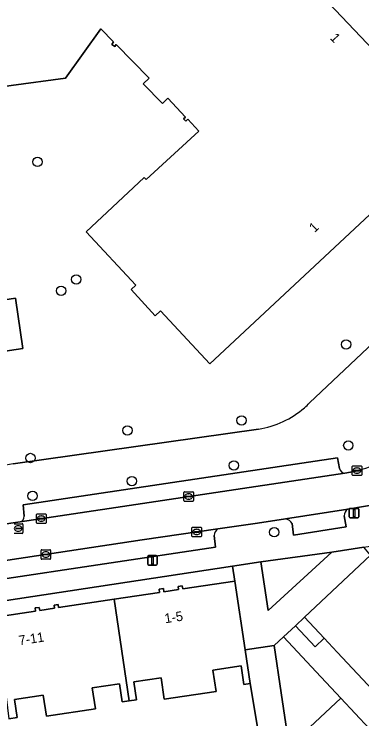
# Model space of a CAD drawing. Extents: x 162344 to 162869, y 381217 to 381818.
# Drawn here: x 162570.6 to 162607, y 381348.2 to 381421.8 of the extents above; entities that cross this region are included whole.
import ezdxf

# ---------------------------------------------------------------- set-up
doc = ezdxf.new("R2010")
doc.units = 0
for name, color, linetype in [('IMGEO_Boom', 7, 'Continuous'), ('IMGEO_Erf', 7, 'Continuous'), ('IMGEO_Kolk', 7, 'Continuous'), ('IMGEO_Lichtmast', 7, 'Continuous'), ('IMGEO_Pand', 7, 'Continuous'), ('IMGEO_Pand_nummerreeks', 7, 'Continuous'), ('IMGEO_Parkeervlak_open', 7, 'Continuous'), ('IMGEO_Rijbaan_lokaal_gesloten', 7, 'Continuous'), ('IMGEO_Rioolput', 7, 'Continuous'), ('IMGEO_Voetpad_open', 7, 'Continuous')]:
    doc.layers.add(name, color=color, linetype=linetype)

msp = doc.modelspace()

# ---------------------------------------------------------------- linework, layer by layer
at = {"layer": 'IMGEO_Boom'}
for centre in [(162573.075, 381406.392), (162577.132, 381394.132), (162575.548, 381392.937), (162605.328, 381387.344), (162594.403, 381379.412), (162582.48, 381378.367), (162605.564, 381376.788), (162572.334, 381375.481), (162593.604, 381374.7), (162582.94, 381373.073), (162572.567, 381371.525), (162597.817, 381367.723)]:
    msp.add_circle(centre, 0.489, dxfattribs=at)
at = {"layer": 'IMGEO_Erf'}
for points in [[(162603.56, 381422.951), (162608.827, 381417.399)], [(162616.655, 381409.149), (162591.074, 381385.317), (162585.928, 381390.841), (162585.389, 381390.339), (162582.851, 381393.064), (162583.337, 381393.517), (162578.148, 381399.087), (162584.24, 381404.762), (162584.436, 381404.551), (162589.953, 381409.618), (162588.787, 381410.858), (162588.584, 381410.651), (162588.35, 381410.881), (162588.56, 381411.078), (162586.71, 381413.045), (162586.136, 381412.488), (162584.135, 381414.545), (162584.732, 381415.127), (162581.294, 381418.66), (162581.163, 381418.454), (162580.845, 381418.667), (162581.033, 381418.928), (162579.712, 381420.286), (162576.009, 381415.134), (162564.593, 381413.622)], [(162601.509, 381381.232), (162620.339, 381398.978), (162622.119, 381400.656)], [(162568.257, 381391.801), (162570.791, 381392.181), (162571.557, 381386.927), (162568.969, 381386.539)], [(162570.548, 381374.856), (162596.18, 381378.489)], [(162597.05, 381341.556), (162595.307, 381351.935), (162594.646, 381351.836), (162594.35, 381353.779), (162591.412, 381353.343), (162591.75, 381351.107), (162586.331, 381350.29), (162585.993, 381352.539), (162583.137, 381352.115), (162583.426, 381350.237), (162582.674, 381350.124), (162581.923, 381350.01), (162581.635, 381351.892), (162578.794, 381351.47), (162579.122, 381349.293), (162574.004, 381348.522), (162573.673, 381350.71), (162570.656, 381350.262), (162570.941, 381348.378), (162570.076, 381348.247)]]:
    msp.add_lwpolyline(points, dxfattribs=at)
for points in [[(162593.693, 381362.637), (162593.458, 381364.187), (162555.599, 381358.447), (162555.828, 381356.926), (162560.046, 381357.562), (162564.264, 381358.199), (162572.881, 381359.499), (162572.832, 381359.826), (162573.257, 381359.89), (162573.306, 381359.563), (162574.858, 381359.797), (162574.809, 381360.124), (162575.234, 381360.188), (162575.283, 381359.861), (162581.074, 381360.735), (162585.843, 381361.454), (162585.794, 381361.781), (162586.229, 381361.846), (162586.278, 381361.519), (162587.83, 381361.753), (162587.781, 381362.08), (162588.206, 381362.144), (162588.255, 381361.817)], [(162604.402, 381355.204), (162603.04, 381356.655), (162602.103, 381355.775), (162600.043, 381357.97), (162598.783, 381356.808), (162602.205, 381353.162), (162604.783, 381350.416), (162607.786, 381347.217), (162610.83, 381343.974), (162613.666, 381340.953), (162618.167, 381336.158), (162620.355, 381338.212)]]:
    msp.add_lwpolyline(points, close=True, dxfattribs=at)
for centre, radius, start, end in [((162594.649, 381388.016), 9.649, 279.12953, 311.01266), ((162594.528, 381388.12), 9.807, 311.1491, 315.38626)]:
    msp.add_arc(centre, radius, start, end, dxfattribs=at)
at = {"layer": 'IMGEO_Kolk'}
for p, q in [((162605.967, 381373.737), (162605.967, 381374.589)), ((162606.042, 381374.663), (162606.894, 381374.663)), ((162606.226, 381374.157), (162606.226, 381374.169)), ((162606.664, 381374.12), (162606.266, 381374.12)), ((162606.269, 381374.206), (162606.667, 381374.206)), ((162606.455, 381374.443), (162606.48, 381374.443)), ((162606.71, 381374.169), (162606.71, 381374.157)), ((162606.968, 381374.589), (162606.968, 381373.737)), ((162606.894, 381373.663), (162606.042, 381373.663)), ((162606.478, 381373.883), (162606.453, 381373.883)), ((162588.373, 381371.03), (162588.373, 381371.882)), ((162588.448, 381371.956), (162589.3, 381371.956)), ((162589.374, 381371.882), (162589.374, 381371.03)), ((162588.632, 381371.45), (162588.632, 381371.462)), ((162589.07, 381371.413), (162588.672, 381371.413)), ((162588.675, 381371.499), (162589.073, 381371.499)), ((162588.884, 381371.176), (162588.859, 381371.176)), ((162588.861, 381371.736), (162588.886, 381371.736)), ((162589.116, 381371.462), (162589.116, 381371.45)), ((162589.3, 381370.956), (162588.448, 381370.956)), ((162573.045, 381369.653), (162573.897, 381369.653)), ((162572.97, 381368.727), (162572.97, 381369.579)), ((162573.229, 381369.147), (162573.229, 381369.159)), ((162573.667, 381369.11), (162573.269, 381369.11)), ((162573.272, 381369.196), (162573.67, 381369.196)), ((162573.481, 381368.873), (162573.456, 381368.873)), ((162573.458, 381369.433), (162573.483, 381369.433)), ((162573.713, 381369.159), (162573.713, 381369.147)), ((162573.971, 381369.579), (162573.971, 381368.727)), ((162573.897, 381368.653), (162573.045, 381368.653)), ((162589.215, 381367.334), (162589.215, 381368.186)), ((162589.29, 381368.26), (162590.142, 381368.26)), ((162590.216, 381368.186), (162590.216, 381367.334)), ((162589.474, 381367.754), (162589.474, 381367.766)), ((162589.912, 381367.717), (162589.514, 381367.717)), ((162589.517, 381367.803), (162589.915, 381367.803)), ((162589.726, 381367.48), (162589.701, 381367.48)), ((162589.703, 381368.04), (162589.728, 381368.04)), ((162589.958, 381367.766), (162589.958, 381367.754)), ((162590.142, 381367.26), (162589.29, 381367.26)), ((162573.449, 381364.981), (162573.449, 381365.833)), ((162573.524, 381365.907), (162574.376, 381365.907)), ((162573.708, 381365.401), (162573.708, 381365.413)), ((162574.146, 381365.364), (162573.748, 381365.364)), ((162573.751, 381365.45), (162574.149, 381365.45)), ((162573.937, 381365.687), (162573.962, 381365.687)), ((162574.192, 381365.413), (162574.192, 381365.401)), ((162574.45, 381365.833), (162574.45, 381364.981)), ((162574.376, 381364.907), (162573.524, 381364.907)), ((162573.96, 381365.127), (162573.935, 381365.127))]:
    msp.add_line(p, q, dxfattribs=at)
for points in [[(162605.967, 381373.737), (162605.967, 381374.589)], [(162606.042, 381374.663), (162606.894, 381374.663)], [(162606.968, 381374.589), (162606.968, 381373.737)], [(162606.894, 381373.663), (162606.042, 381373.663)], [(162588.373, 381371.03), (162588.373, 381371.882)], [(162588.448, 381371.956), (162589.3, 381371.956)], [(162589.374, 381371.882), (162589.374, 381371.03)], [(162589.3, 381370.956), (162588.448, 381370.956)], [(162573.045, 381369.653), (162573.897, 381369.653)], [(162572.97, 381368.727), (162572.97, 381369.579)], [(162573.971, 381369.579), (162573.971, 381368.727)], [(162573.897, 381368.653), (162573.045, 381368.653)], [(162589.215, 381367.334), (162589.215, 381368.186)], [(162589.29, 381368.26), (162590.142, 381368.26)], [(162590.216, 381368.186), (162590.216, 381367.334)], [(162590.142, 381367.26), (162589.29, 381367.26)], [(162573.449, 381364.981), (162573.449, 381365.833)], [(162573.524, 381365.907), (162574.376, 381365.907)], [(162574.45, 381365.833), (162574.45, 381364.981)], [(162574.376, 381364.907), (162573.524, 381364.907)]]:
    msp.add_lwpolyline(points, dxfattribs=at)
for centre, radius, start, end in [((162606.044, 381374.587), 0.0765, 91.55205, 178.44795), ((162606.044, 381374.587), 0.0765, 91.55205, 178.44795), ((162606.266, 381374.166), 0.0403, 85.87752, 175.75265), ((162606.263, 381374.156), 0.0366, 178.93798, 274.71019), ((162606.667, 381374.163), 0.043, 264.86636, 352.45326), ((162606.671, 381374.168), 0.0386, 1.73085, 96.63898), ((162606.892, 381374.587), 0.0765, 1.55205, 88.44795), ((162606.892, 381374.587), 0.0765, 1.55205, 88.44795), ((162606.044, 381373.739), 0.0765, 181.55205, 268.44795), ((162606.044, 381373.739), 0.0765, 181.55205, 268.44795), ((162606.892, 381373.739), 0.0765, 271.55205, 358.44795), ((162606.892, 381373.739), 0.0765, 271.55205, 358.44795), ((162588.45, 381371.88), 0.0765, 91.55205, 178.44795), ((162588.45, 381371.88), 0.0765, 91.55205, 178.44795), ((162589.298, 381371.88), 0.0765, 1.55205, 88.44795), ((162589.298, 381371.88), 0.0765, 1.55205, 88.44795), ((162588.672, 381371.459), 0.0403, 85.87752, 175.75265), ((162588.669, 381371.449), 0.0366, 178.93798, 274.71019), ((162589.073, 381371.456), 0.043, 264.86636, 352.45326), ((162589.077, 381371.461), 0.0386, 1.73085, 96.63898), ((162588.45, 381371.032), 0.0765, 181.55205, 268.44795), ((162588.45, 381371.032), 0.0765, 181.55205, 268.44795), ((162589.298, 381371.032), 0.0765, 271.55205, 358.44795), ((162589.298, 381371.032), 0.0765, 271.55205, 358.44795), ((162573.047, 381369.577), 0.0765, 91.55205, 178.44795), ((162573.047, 381369.577), 0.0765, 91.55205, 178.44795), ((162573.895, 381369.577), 0.0765, 1.55205, 88.44795), ((162573.895, 381369.577), 0.0765, 1.55205, 88.44795), ((162573.269, 381369.156), 0.0403, 85.87752, 175.75265), ((162573.266, 381369.146), 0.0366, 178.93798, 274.71019), ((162573.67, 381369.153), 0.043, 264.86636, 352.45326), ((162573.674, 381369.158), 0.0386, 1.73085, 96.63898), ((162573.047, 381368.729), 0.0765, 181.55205, 268.44795), ((162573.047, 381368.729), 0.0765, 181.55205, 268.44795), ((162573.895, 381368.729), 0.0765, 271.55205, 358.44795), ((162573.895, 381368.729), 0.0765, 271.55205, 358.44795), ((162589.292, 381368.184), 0.0765, 91.55205, 178.44795), ((162589.292, 381368.184), 0.0765, 91.55205, 178.44795), ((162590.14, 381368.184), 0.0765, 1.55205, 88.44795), ((162590.14, 381368.184), 0.0765, 1.55205, 88.44795), ((162589.514, 381367.763), 0.0403, 85.87752, 175.75265), ((162589.511, 381367.753), 0.0366, 178.93798, 274.71019), ((162589.915, 381367.76), 0.043, 264.86636, 352.45326), ((162589.919, 381367.765), 0.0386, 1.73085, 96.63898), ((162589.292, 381367.336), 0.0765, 181.55205, 268.44795), ((162589.292, 381367.336), 0.0765, 181.55205, 268.44795), ((162590.14, 381367.336), 0.0765, 271.55205, 358.44795), ((162590.14, 381367.336), 0.0765, 271.55205, 358.44795), ((162573.526, 381365.831), 0.0765, 91.55205, 178.44795), ((162573.526, 381365.831), 0.0765, 91.55205, 178.44795), ((162573.748, 381365.41), 0.0403, 85.87752, 175.75265), ((162573.745, 381365.4), 0.0366, 178.93798, 274.71019), ((162574.149, 381365.407), 0.043, 264.86636, 352.45326), ((162574.153, 381365.412), 0.0386, 1.73085, 96.63898), ((162574.374, 381365.831), 0.0765, 1.55205, 88.44795), ((162574.374, 381365.831), 0.0765, 1.55205, 88.44795), ((162573.526, 381364.983), 0.0765, 181.55205, 268.44795), ((162573.526, 381364.983), 0.0765, 181.55205, 268.44795), ((162574.374, 381364.983), 0.0765, 271.55205, 358.44795), ((162574.374, 381364.983), 0.0765, 271.55205, 358.44795)]:
    msp.add_arc(centre, radius, start, end, dxfattribs=at)
for centre, major_axis, ratio, start_param, end_param in [((162606.454, 381374.163), (-0.387, 0.002), 0.722429, 4.712389, 7.853982), ((162606.479, 381374.163), (-0.39, 0.002), 0.717154, 1.570796, 4.712389), ((162588.86, 381371.456), (-0.387, 0.002), 0.722429, 4.712389, 7.853982), ((162588.885, 381371.456), (-0.39, 0.002), 0.717154, 1.570796, 4.712389), ((162573.457, 381369.153), (-0.387, 0.002), 0.722429, 4.712389, 7.853982), ((162573.482, 381369.153), (-0.39, 0.002), 0.717154, 1.570796, 4.712389), ((162589.702, 381367.76), (-0.387, 0.002), 0.722429, 4.712389, 7.853982), ((162589.727, 381367.76), (-0.39, 0.002), 0.717154, 1.570796, 4.712389), ((162573.936, 381365.407), (-0.387, 0.002), 0.722429, 4.712389, 7.853982), ((162573.961, 381365.407), (-0.39, 0.002), 0.717154, 1.570796, 4.712389)]:
    msp.add_ellipse(centre, major_axis=major_axis, ratio=ratio, start_param=start_param, end_param=end_param, dxfattribs=at)
at = {"layer": 'IMGEO_Lichtmast'}
for p, q in [((162605.669, 381369.326), (162605.669, 381370.126)), ((162605.669, 381370.126), (162605.669, 381369.326)), ((162605.769, 381370.226), (162606.559, 381370.226)), ((162606.559, 381370.226), (162605.769, 381370.226)), ((162606.659, 381370.126), (162606.659, 381369.326)), ((162606.659, 381369.326), (162606.659, 381370.126)), ((162606.559, 381369.226), (162605.769, 381369.226)), ((162605.769, 381369.226), (162606.559, 381369.226)), ((162584.594, 381364.386), (162584.594, 381365.186)), ((162584.594, 381365.186), (162584.594, 381364.386)), ((162584.694, 381365.286), (162585.484, 381365.286)), ((162585.484, 381365.286), (162584.694, 381365.286)), ((162585.584, 381365.186), (162585.584, 381364.386)), ((162585.584, 381364.386), (162585.584, 381365.186)), ((162585.484, 381364.286), (162584.694, 381364.286)), ((162584.694, 381364.286), (162585.484, 381364.286))]:
    msp.add_line(p, q, dxfattribs=at)
for points in [[(162606.089, 381370.101), (162606.239, 381370.101), (162606.239, 381369.351), (162606.089, 381369.351), (162606.089, 381370.101)], [(162585.014, 381365.161), (162585.164, 381365.161), (162585.164, 381364.411), (162585.014, 381364.411), (162585.014, 381365.161)]]:
    msp.add_lwpolyline(points, dxfattribs=at)
for centre, start, end in [((162605.769, 381370.126), 90, 180), ((162605.769, 381370.126), 90, 180), ((162606.559, 381370.126), 0, 90), ((162606.559, 381370.126), 360, 90), ((162605.769, 381369.326), 180, 270), ((162605.769, 381369.326), 180, 270), ((162606.559, 381369.326), 270, 0), ((162606.559, 381369.326), 270, 0), ((162584.694, 381365.186), 90, 180), ((162584.694, 381365.186), 90, 180), ((162585.484, 381365.186), 0, 90), ((162585.484, 381365.186), 360, 90), ((162584.694, 381364.386), 180, 270), ((162584.694, 381364.386), 180, 270), ((162585.484, 381364.386), 270, 0), ((162585.484, 381364.386), 270, 0)]:
    msp.add_arc(centre, 0.1, start, end, dxfattribs=at)
at = {"layer": 'IMGEO_Pand'}
for points in [[(162608.827, 381417.399), (162603.56, 381422.951)], [(162564.593, 381413.622), (162576.009, 381415.134), (162579.712, 381420.286), (162581.033, 381418.928), (162580.845, 381418.667), (162581.163, 381418.454), (162581.294, 381418.66), (162584.732, 381415.127), (162584.135, 381414.545), (162586.136, 381412.488), (162586.71, 381413.045), (162588.56, 381411.078), (162588.35, 381410.881), (162588.584, 381410.651), (162588.787, 381410.858), (162589.953, 381409.618), (162584.436, 381404.551), (162584.24, 381404.762), (162578.148, 381399.087), (162583.337, 381393.517), (162582.851, 381393.064), (162585.389, 381390.339), (162585.928, 381390.841), (162591.074, 381385.317), (162616.655, 381409.149)]]:
    msp.add_lwpolyline(points, dxfattribs=at)
for points in [[(162568.969, 381386.539), (162571.557, 381386.927), (162570.791, 381392.181), (162568.257, 381391.801), (162568.071, 381391.773), (162568.838, 381386.519)], [(162607.896, 381365.343), (162600.979, 381358.849), (162603.04, 381356.655), (162604.402, 381355.204), (162620.355, 381338.212), (162623.628, 381341.285), (162627.163, 381344.605), (162627.272, 381344.707)], [(162593.693, 381362.637), (162588.255, 381361.817), (162588.206, 381362.144), (162587.781, 381362.08), (162587.83, 381361.753), (162586.278, 381361.519), (162586.229, 381361.846), (162585.794, 381361.781), (162585.843, 381361.454), (162581.074, 381360.735), (162582.674, 381350.124), (162583.426, 381350.237), (162583.137, 381352.115), (162585.993, 381352.539), (162586.331, 381350.29), (162591.75, 381351.107), (162591.412, 381353.343), (162594.35, 381353.779), (162594.646, 381351.836), (162595.307, 381351.935), (162594.778, 381355.441)], [(162581.074, 381360.735), (162575.283, 381359.861), (162575.234, 381360.188), (162574.809, 381360.124), (162574.858, 381359.797), (162573.306, 381359.563), (162573.257, 381359.89), (162572.832, 381359.826), (162572.881, 381359.499), (162564.264, 381358.199), (162565.34, 381351.082), (162569.652, 381351.706), (162570.076, 381348.247), (162570.941, 381348.378), (162570.656, 381350.262), (162573.673, 381350.71), (162574.004, 381348.522), (162579.122, 381349.293), (162578.794, 381351.47), (162581.635, 381351.892), (162581.923, 381350.01), (162582.674, 381350.124)], [(162600.979, 381358.849), (162600.043, 381357.97), (162602.103, 381355.775), (162603.04, 381356.655)], [(162602.205, 381353.162), (162598.783, 381356.808), (162597.826, 381355.908), (162598.554, 381350.962), (162599.38, 381345.353), (162604.783, 381350.416)], [(162607.786, 381347.217), (162604.783, 381350.416), (162599.38, 381345.353), (162600.158, 381340.069)]]:
    msp.add_lwpolyline(points, close=True, dxfattribs=at)
at = {"layer": 'IMGEO_Parkeervlak_open'}
for points in [[(162604.653, 381374.394), (162604.442, 381375.51), (162571.586, 381370.597), (162571.671, 381369.405)], [(162571.256, 381368.82), (162605.213, 381373.889)], [(162605.497, 381370.151), (162598.994, 381369.138)], [(162599.705, 381368.632), (162599.828, 381367.427), (162605.344, 381368.279), (162605.12, 381369.446)], [(162591.93, 381368.082), (162584.005, 381366.935), (162567.642, 381364.451)], [(162568.27, 381363.869), (162568.456, 381362.69), (162591.675, 381366.161), (162591.526, 381367.391)]]:
    msp.add_lwpolyline(points, dxfattribs=at)
for centre, radius, start, end in [((162605.245, 381374.487), 0.599, 188.96174, 266.95088), ((162606.084, 381369.384), 0.966, 127.42795, 176.30061), ((162571.158, 381369.329), 0.518, 280.85333, 8.44276), ((162598.741, 381368.03), 1.136, 31.9769, 77.14619), ((162592.583, 381367.236), 1.069, 127.69185, 171.68192)]:
    msp.add_arc(centre, radius, start, end, dxfattribs=at)
at = {"layer": 'IMGEO_Rijbaan_lokaal_gesloten'}
for points in [[(162591.93, 381368.082), (162592.402, 381368.151), (162596.083, 381368.685), (162598.994, 381369.138), (162605.497, 381370.151), (162607.148, 381370.42), (162608.866, 381370.698), (162614.045, 381372.134), (162617.725, 381373.904), (162624.41, 381379.449), (162626.115, 381381.23), (162639.652, 381395.21)], [(162606.17, 381374.078), (162605.213, 381373.889), (162571.256, 381368.82), (162570.283, 381368.666), (162564.322, 381367.722), (162563.948, 381367.663), (162563.582, 381367.608), (162535.111, 381363.294), (162534.146, 381363.156), (162524.421, 381361.762), (162523.981, 381361.699), (162522.366, 381361.45), (162515.899, 381360.453), (162513.321, 381360.055), (162512.415, 381359.993)], [(162515.923, 381356.718), (162517.595, 381356.95), (162517.749, 381356.974), (162530.674, 381358.967), (162533.107, 381359.314), (162536.811, 381359.842), (162540.681, 381360.393), (162547.682, 381361.428), (162548.639, 381361.573), (162552.34, 381362.133), (162555.362, 381362.591), (162558.977, 381363.139), (162563.502, 381363.824), (162567.132, 381364.374), (162567.642, 381364.451), (162584.005, 381366.935), (162591.93, 381368.082)]]:
    msp.add_lwpolyline(points, dxfattribs=at)
msp.add_arc((162602.584, 381388.789), 15.141, 283.69796, 309.06214, dxfattribs=at)
at = {"layer": 'IMGEO_Rioolput'}
for p, q in [((162570.628, 381368.616), (162571.48, 381368.616)), ((162570.812, 381368.11), (162570.812, 381368.122)), ((162570.855, 381368.159), (162571.253, 381368.159)), ((162571.041, 381368.396), (162571.066, 381368.396)), ((162571.296, 381368.122), (162571.296, 381368.11)), ((162571.554, 381368.542), (162571.554, 381367.69)), ((162571.48, 381367.616), (162570.628, 381367.616)), ((162571.25, 381368.073), (162570.852, 381368.073)), ((162571.064, 381367.836), (162571.039, 381367.836))]:
    msp.add_line(p, q, dxfattribs=at)
for points in [[(162570.628, 381368.616), (162571.48, 381368.616)], [(162571.554, 381368.542), (162571.554, 381367.69)], [(162571.48, 381367.616), (162570.628, 381367.616)]]:
    msp.add_lwpolyline(points, dxfattribs=at)
for centre, radius, start, end in [((162570.852, 381368.119), 0.0403, 85.87752, 175.75265), ((162571.257, 381368.121), 0.0386, 1.73085, 96.63898), ((162571.478, 381368.54), 0.0765, 1.55205, 88.44795), ((162571.478, 381368.54), 0.0765, 1.55205, 88.44795), ((162570.849, 381368.109), 0.0366, 178.93798, 274.71019), ((162571.253, 381368.116), 0.043, 264.86636, 352.45326), ((162571.478, 381367.692), 0.0765, 271.55205, 358.44795), ((162571.478, 381367.692), 0.0765, 271.55205, 358.44795)]:
    msp.add_arc(centre, radius, start, end, dxfattribs=at)
for centre, major_axis, ratio, start_param, end_param in [((162571.04, 381368.116), (-0.387, 0.002), 0.722429, 4.712389, 7.853982), ((162571.065, 381368.116), (-0.39, 0.002), 0.717154, 1.570796, 4.712389)]:
    msp.add_ellipse(centre, major_axis=major_axis, ratio=ratio, start_param=start_param, end_param=end_param, dxfattribs=at)
at = {"layer": 'IMGEO_Voetpad_open'}
for points in [[(162633.892, 381403.758), (162633.239, 381404.624), (162630.243, 381407.839), (162622.119, 381400.656), (162620.339, 381398.978), (162601.509, 381381.232)], [(162596.18, 381378.489), (162570.548, 381374.856), (162569.375, 381374.68), (162565.802, 381374.16), (162563.919, 381373.876), (162551.336, 381371.979), (162545.689, 381371.128), (162541.544, 381370.503), (162528.79, 381368.58), (162528.573, 381367.017), (162509.669, 381369.232), (162513.321, 381360.055), (162515.899, 381360.453)], [(162571.671, 381369.405), (162571.586, 381370.597), (162604.442, 381375.51)], [(162604.442, 381375.51), (162604.653, 381374.394)], [(162605.213, 381373.889), (162606.17, 381374.078)], [(162608.866, 381370.698), (162607.148, 381370.42), (162605.497, 381370.151)], [(162598.994, 381369.138), (162596.083, 381368.685), (162592.402, 381368.151), (162591.93, 381368.082)], [(162605.12, 381369.446), (162605.344, 381368.279), (162599.828, 381367.427), (162599.705, 381368.632)], [(162563.582, 381367.608), (162563.948, 381367.663), (162564.322, 381367.722), (162570.283, 381368.666), (162571.256, 381368.82)], [(162513.485, 381355.838), (162515.721, 381347.587), (162519.471, 381348.712), (162526.112, 381350.704), (162526.582, 381354.07), (162532.585, 381354.976), (162540.878, 381356.227), (162547.044, 381357.157), (162548.922, 381357.44), (162555.599, 381358.447), (162593.458, 381364.187), (162596.425, 381364.637), (162603.853, 381365.663), (162607.179, 381366.158), (162618.388, 381367.898)], [(162591.526, 381367.391), (162591.675, 381366.161), (162568.456, 381362.69), (162568.27, 381363.869)], [(162599.38, 381345.353), (162598.554, 381350.962), (162597.826, 381355.908), (162594.778, 381355.441), (162595.307, 381351.935), (162597.05, 381341.556)]]:
    msp.add_lwpolyline(points, dxfattribs=at)
for points in [[(162607.896, 381365.343), (162607.179, 381366.158), (162603.853, 381365.663), (162597.196, 381359.556), (162596.425, 381364.637), (162593.458, 381364.187), (162593.693, 381362.637), (162594.778, 381355.441), (162597.826, 381355.908), (162598.783, 381356.808), (162600.043, 381357.97), (162600.979, 381358.849)], [(162596.425, 381364.637), (162597.196, 381359.556), (162603.853, 381365.663)]]:
    msp.add_lwpolyline(points, close=True, dxfattribs=at)
for centre, radius, start, end in [((162594.649, 381388.016), 9.649, 279.12953, 311.01266), ((162594.528, 381388.12), 9.807, 311.1491, 315.38626), ((162602.584, 381388.789), 15.141, 283.69796, 309.06214), ((162605.245, 381374.487), 0.599, 188.96174, 266.95088), ((162606.084, 381369.384), 0.966, 127.42795, 176.30061), ((162571.158, 381369.329), 0.518, 280.85333, 8.44276), ((162598.741, 381368.03), 1.136, 31.9769, 77.14619), ((162592.583, 381367.236), 1.069, 127.69185, 171.68192)]:
    msp.add_arc(centre, radius, start, end, dxfattribs=at)

# ---------------------------------------------------------------- texts
at = {"layer": 'IMGEO_Pand_nummerreeks'}
for s, rotation, p in [('1', 313.49103, (162603.594, 381419.283)), ('1', 42.97183, (162602.029, 381398.967)), ('1-5', 8.57145, (162586.429, 381358.225)), ('7-11', 8.57718, (162571.188, 381355.926))]:
    msp.add_text(s, height=1, rotation=rotation, dxfattribs=at).set_placement(p)

doc.saveas('drawing.dxf')
